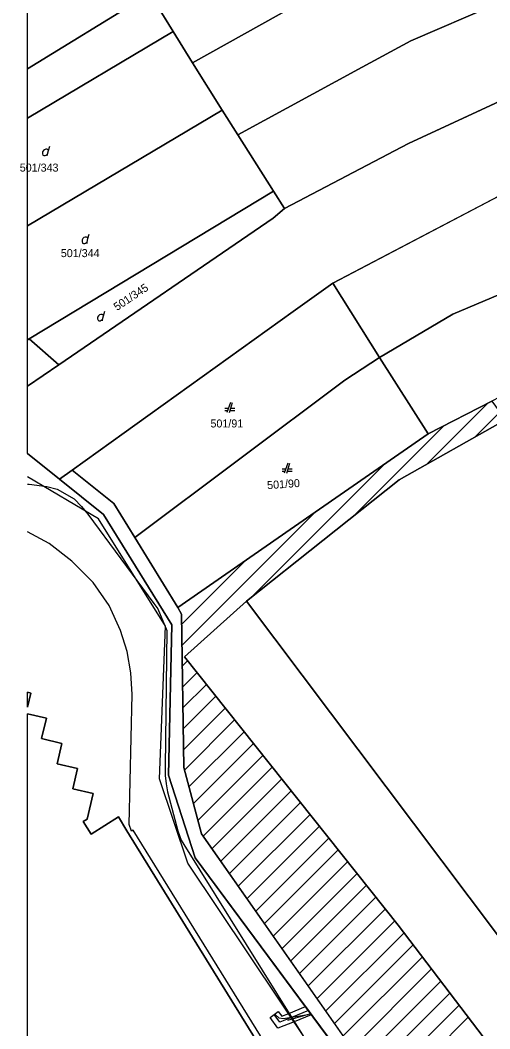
# Model space of a CAD drawing. Extents: x -264309 to -263505, y -1242443 to -1241763.
# Drawn here: x -264309.2 to -264215.4, y -1242302.6 to -1242101 of the extents above; entities that cross this region are included whole.
import ezdxf

# ---------------------------------------------------------------- set-up
doc = ezdxf.new("R2010")
doc.units = 0
for name, color, linetype in [('KN_2019_08_16', 7, 'Continuous'), ('KN_2019_08_16_KLADPAR', 7, 'Continuous'), ('KN_2019_08_16_ZAPPAR', 7, 'Continuous'), ('SRAFY_PARCELY', 7, 'Continuous')]:
    doc.layers.add(name, color=color, linetype=linetype)

msp = doc.modelspace()

# ---------------------------------------------------------------- linework, layer by layer
at = {"layer": 'KN_2019_08_16'}
msp.add_line((-264252.15, -1242299.89), (-264255.82, -1242300.96), dxfattribs=at)
for points in [[(-264307.74, -1242340.12), (-264306.25, -1242339.09), (-264251.27, -1242306.11), (-264275.75, -1242269.48), (-264281.42, -1242252.63), (-264280.19, -1242222.16), (-264293.61, -1242200.69), (-264307.74, -1242192.28)], [(-264251.64, -1242298.97), (-264255.03, -1242300.37), (-264257.35, -1242301.31), (-264258.47, -1242299.75)], [(-264251.16, -1242299.61), (-264252.15, -1242299.89), (-264256.65, -1242300.61), (-264257.51, -1242300.5), (-264258.32, -1242299.77)]]:
    msp.add_lwpolyline(points, dxfattribs=at)
msp.add_lwpolyline([(-264250.88, -1242299.99), (-264251.12, -1242299.83), (-264254.5, -1242301.21), (-264257.75, -1242302.51), (-264259.27, -1242300.35), (-264258.47, -1242299.75), (-264257.67, -1242299.15), (-264256.96, -1242300.09), (-264255.56, -1242299.52), (-264252.24, -1242298.16), (-264251.64, -1242298.97)], close=True, dxfattribs=at)
at = {"layer": 'KN_2019_08_16_KLADPAR'}
for p, q in [((-264307.74, -1242110.73), (-264307.74, -1242064.3)), ((-264307.74, -1242110.73), (-264283.31, -1242095.71)), ((-264283.31, -1242095.71), (-264307.74, -1242110.73)), ((-264283.31, -1242095.71), (-264278.66, -1242103.27)), ((-264278.66, -1242103.27), (-264307.74, -1242120.6)), ((-264307.74, -1242120.6), (-264278.66, -1242103.27)), ((-264278.66, -1242103.27), (-264274.79, -1242109.56)), ((-264274.79, -1242109.56), (-264268.86, -1242119.03)), ((-264231.66, -1242125.67), (-264195.32, -1242108.83)), ((-264307.74, -1242120.6), (-264307.74, -1242110.73)), ((-264268.86, -1242119.03), (-264307.74, -1242142.14)), ((-264307.74, -1242142.14), (-264268.86, -1242119.03)), ((-264268.86, -1242119.03), (-264265.78, -1242123.95)), ((-264307.74, -1242142.14), (-264307.74, -1242120.6)), ((-264265.78, -1242123.95), (-264258.61, -1242135.22)), ((-264303.59, -1242127.11), (-264303.32, -1242126.21)), ((-264256.42, -1242138.67), (-264231.66, -1242125.67)), ((-264207.96, -1242133.21), (-264246.81, -1242153.57)), ((-264258.61, -1242135.22), (-264307.46, -1242164.74)), ((-264301.53, -1242169.89), (-264258.73, -1242140.63)), ((-264258.73, -1242140.63), (-264256.42, -1242138.67)), ((-264307.74, -1242164.9), (-264307.74, -1242142.14)), ((-264295.7, -1242144.67), (-264295.43, -1242143.77)), ((-264246.81, -1242153.57), (-264254.72, -1242159.25)), ((-264254.72, -1242159.25), (-264298.85, -1242190.99)), ((-264292.59, -1242160.11), (-264292.32, -1242159.21)), ((-264307.46, -1242164.74), (-264307.74, -1242164.9)), ((-264307.74, -1242164.9), (-264307.46, -1242164.74)), ((-264307.46, -1242164.74), (-264301.53, -1242169.89)), ((-264307.74, -1242174.19), (-264307.74, -1242164.9)), ((-264301.53, -1242169.89), (-264307.74, -1242174.19)), ((-264307.74, -1242174.19), (-264301.53, -1242169.89)), ((-264307.74, -1242187.65), (-264307.74, -1242174.19)), ((-264267.65, -1242178.64), (-264268.33, -1242178.64)), ((-264267.23, -1242177.44), (-264267.93, -1242179.44)), ((-264267.43, -1242179.44), (-264266.83, -1242177.44)), ((-264266.33, -1242178.64), (-264267.19, -1242178.64)), ((-264268.33, -1242179.04), (-264267.79, -1242179.04)), ((-264267.31, -1242179.04), (-264266.33, -1242179.04)), ((-264301.35, -1242192.78), (-264307.74, -1242187.65)), ((-264301.35, -1242192.78), (-264298.85, -1242190.99)), ((-264298.85, -1242190.99), (-264301.35, -1242192.78)), ((-264298.85, -1242190.99), (-264290.49, -1242197.63)), ((-264256.22, -1242190.76), (-264256.9, -1242190.76)), ((-264255.8, -1242189.56), (-264256.5, -1242191.56)), ((-264256, -1242191.56), (-264255.4, -1242189.56)), ((-264254.9, -1242190.76), (-264255.76, -1242190.76)), ((-264292.61, -1242199.8), (-264301.35, -1242192.78)), ((-264256.9, -1242191.16), (-264256.36, -1242191.16)), ((-264255.88, -1242191.16), (-264254.9, -1242191.16)), ((-264290.49, -1242197.63), (-264286.35, -1242204.42)), ((-264278.94, -1242221.86), (-264292.61, -1242199.8)), ((-264286.35, -1242204.42), (-264277.77, -1242218.42)), ((-264277.77, -1242218.42), (-264276.98, -1242219.72)), ((-264276.98, -1242219.72), (-264276.57, -1242250.38)), ((-264279.62, -1242251.94), (-264278.94, -1242221.86)), ((-264307.74, -1242238.35), (-264307.74, -1242235.36)), ((-264307.74, -1242235.36), (-264307.08, -1242235.52)), ((-264307.08, -1242235.52), (-264307.74, -1242238.35)), ((-264307.74, -1242332.8), (-264307.74, -1242239.64)), ((-264307.74, -1242239.64), (-264303.98, -1242240.53)), ((-264303.98, -1242240.53), (-264304.95, -1242244.6)), ((-264304.95, -1242244.6), (-264300.88, -1242245.57)), ((-264300.88, -1242245.57), (-264301.83, -1242249.65)), ((-264301.83, -1242249.65), (-264297.75, -1242250.6)), ((-264297.75, -1242250.6), (-264298.7, -1242254.62)), ((-264276.57, -1242250.38), (-264272.98, -1242263.62)), ((-264274.26, -1242268.44), (-264279.62, -1242251.94)), ((-264298.7, -1242254.62), (-264294.68, -1242255.57)), ((-264294.68, -1242255.57), (-264295.87, -1242260.74)), ((-264295.87, -1242260.74), (-264296.63, -1242261.2)), ((-264296.63, -1242261.2), (-264295.08, -1242263.7)), ((-264295.08, -1242263.7), (-264289.57, -1242260.22)), ((-264289.57, -1242260.22), (-264287.91, -1242263.04)), ((-264287.91, -1242263.04), (-264262.22, -1242304.65)), ((-264272.98, -1242263.62), (-264240.46, -1242310.08)), ((-264240.44, -1242314.08), (-264274.26, -1242268.44))]:
    msp.add_line(p, q, dxfattribs=at)
for points in [[(-264232.73, -1242069.28), (-264215.64, -1242060.08), (-264203.07, -1242053.35), (-264189.98, -1242046.97), (-264181.27, -1242051.82), (-264173.43, -1242055.54), (-264168.01, -1242057.92), (-264176.29, -1242061.5), (-264207.3, -1242075.14), (-264227.48, -1242084.41), (-264254.05, -1242097.99), (-264274.79, -1242109.56), (-264278.66, -1242103.27), (-264283.31, -1242095.71), (-264271.31, -1242088.83)], [(-264168.01, -1242057.92), (-264161.74, -1242060.05), (-264155.45, -1242062), (-264148.68, -1242063.74), (-264141.87, -1242065.13), (-264136.47, -1242066.18), (-264140.89, -1242068), (-264182.59, -1242084.17), (-264197.75, -1242090.71), (-264231.21, -1242105.15), (-264240.95, -1242110.43), (-264265.78, -1242123.95), (-264268.86, -1242119.03), (-264274.79, -1242109.56), (-264254.05, -1242097.99), (-264227.48, -1242084.41), (-264207.3, -1242075.14), (-264176.29, -1242061.5)], [(-264136.47, -1242066.18), (-264126.66, -1242067.07), (-264113.43, -1242067.44), (-264093.07, -1242066.63), (-264091, -1242071.24), (-264106.54, -1242077.18), (-264118.83, -1242081.48), (-264143.3, -1242090.1), (-264171.23, -1242099.67), (-264195.32, -1242108.83), (-264231.66, -1242125.67), (-264256.42, -1242138.67), (-264258.61, -1242135.22), (-264265.78, -1242123.95), (-264240.95, -1242110.43), (-264231.21, -1242105.15), (-264197.75, -1242090.71), (-264182.59, -1242084.17), (-264140.89, -1242068)], [(-264246.81, -1242153.57), (-264207.96, -1242133.21), (-264176.83, -1242121.28), (-264120.91, -1242102.78), (-264081.08, -1242089.93), (-264076.9, -1242098.2), (-264076.93, -1242111.1), (-264102.41, -1242118.92), (-264128.45, -1242126.51), (-264158.28, -1242134.19), (-264188.56, -1242145.27), (-264215.11, -1242156.51), (-264222.8, -1242159.81), (-264237.43, -1242168.42)], [(-264076.93, -1242111.1), (-264076.98, -1242129.46), (-264076.3, -1242133.7), (-264095.55, -1242140.08), (-264157.05, -1242153.68), (-264195.05, -1242168.92), (-264211.96, -1242175.6), (-264215.03, -1242177.17), (-264227.71, -1242183.68), (-264237.43, -1242168.42), (-264222.8, -1242159.81), (-264215.11, -1242156.51), (-264188.56, -1242145.27), (-264158.28, -1242134.19), (-264128.45, -1242126.51), (-264102.41, -1242118.92)], [(-264307.46, -1242164.74), (-264258.61, -1242135.22), (-264256.42, -1242138.67), (-264258.73, -1242140.63), (-264301.53, -1242169.89)], [(-264298.85, -1242190.99), (-264254.72, -1242159.25), (-264246.81, -1242153.57), (-264237.43, -1242168.42), (-264244.4, -1242173), (-264286.35, -1242204.42), (-264290.49, -1242197.63)], [(-264237.43, -1242168.42), (-264227.71, -1242183.68), (-264255.3, -1242202.84), (-264277.77, -1242218.42), (-264286.35, -1242204.42), (-264244.4, -1242173)], [(-264264.01, -1242217.15), (-264233.51, -1242192.88), (-264212.29, -1242180.92), (-264137.78, -1242284.52), (-264187.74, -1242315.7), (-264213.92, -1242283.84)], [(-264187.74, -1242315.7), (-264201.06, -1242324.01), (-264208.73, -1242314.82), (-264233.72, -1242281.89), (-264276.4, -1242228.3), (-264264.01, -1242217.15), (-264213.92, -1242283.84)]]:
    msp.add_lwpolyline(points, close=True, dxfattribs=at)
for points in [[(-264303.77, -1242128.1), (-264303.77, -1242127.83), (-264303.59, -1242127.11), (-264303.68, -1242126.93), (-264303.86, -1242126.84), (-264304.13, -1242126.84), (-264304.4, -1242126.93), (-264304.58, -1242127.11), (-264304.76, -1242127.38), (-264304.76, -1242127.74), (-264304.67, -1242128.01), (-264304.49, -1242128.1), (-264304.22, -1242128.1), (-264304.04, -1242128.01), (-264303.77, -1242127.83)], [(-264295.88, -1242145.66), (-264295.88, -1242145.39), (-264295.7, -1242144.67), (-264295.79, -1242144.49), (-264295.97, -1242144.4), (-264296.24, -1242144.4), (-264296.51, -1242144.49), (-264296.69, -1242144.67), (-264296.87, -1242144.94), (-264296.87, -1242145.3), (-264296.78, -1242145.57), (-264296.6, -1242145.66), (-264296.33, -1242145.66), (-264296.15, -1242145.57), (-264295.88, -1242145.39)], [(-264292.77, -1242161.1), (-264292.77, -1242160.83), (-264292.59, -1242160.11), (-264292.68, -1242159.93), (-264292.86, -1242159.84), (-264293.13, -1242159.84), (-264293.4, -1242159.93), (-264293.58, -1242160.11), (-264293.76, -1242160.38), (-264293.76, -1242160.74), (-264293.67, -1242161.01), (-264293.49, -1242161.1), (-264293.22, -1242161.1), (-264293.04, -1242161.01), (-264292.77, -1242160.83)], [(-264240.46, -1242310.08), (-264272.98, -1242263.62), (-264276.57, -1242250.38), (-264276.98, -1242219.72), (-264277.77, -1242218.42), (-264255.3, -1242202.84), (-264227.71, -1242183.68), (-264215.03, -1242177.17), (-264212.29, -1242180.92), (-264233.51, -1242192.88), (-264264.01, -1242217.15), (-264276.4, -1242228.3), (-264233.72, -1242281.89), (-264208.73, -1242314.82)], [(-264307.74, -1242187.65), (-264301.35, -1242192.78), (-264292.61, -1242199.8), (-264278.94, -1242221.86), (-264279.62, -1242251.94), (-264274.26, -1242268.44), (-264240.44, -1242314.08)], [(-264307.74, -1242238.35), (-264307.08, -1242235.52), (-264307.74, -1242235.36)], [(-264287.91, -1242263.04), (-264289.57, -1242260.22), (-264295.08, -1242263.7), (-264296.63, -1242261.2), (-264295.87, -1242260.74), (-264294.68, -1242255.57), (-264298.7, -1242254.62), (-264297.75, -1242250.6), (-264301.83, -1242249.65), (-264300.88, -1242245.57), (-264304.95, -1242244.6), (-264303.98, -1242240.53), (-264307.74, -1242239.64)], [(-264307.74, -1242332.8), (-264294.78, -1242324.78), (-264285.87, -1242319.27), (-264284.51, -1242318.43), (-264262.22, -1242304.65), (-264287.91, -1242263.04)]]:
    msp.add_lwpolyline(points, dxfattribs=at)
at = {"layer": 'KN_2019_08_16_ZAPPAR'}
for p, q in [((-264295.7, -1242199.76), (-264282.5, -1242217.61)), ((-264291.44, -1242218.02), (-264294.67, -1242213.4)), ((-264276.56, -1242265.77), (-264251.67, -1242305.76))]:
    msp.add_line(p, q, dxfattribs=at)
for points in [[(-264307.74, -1242193.79), (-264307.44, -1242193.76), (-264303.91, -1242194.2), (-264301.85, -1242194.77), (-264298.47, -1242196.7), (-264296.96, -1242198.2), (-264295.7, -1242199.76)], [(-264294.67, -1242213.4), (-264298.91, -1242209.14), (-264303.46, -1242205.59), (-264307.74, -1242203.26)], [(-264294.08, -1242327.76), (-264281.99, -1242320.38), (-264276.84, -1242315.01), (-264261.64, -1242305.63), (-264261.11, -1242304.9), (-264261.26, -1242304), (-264286.65, -1242262.93), (-264286.99, -1242263.13), (-264287.49, -1242261.77), (-264286.83, -1242235.8), (-264287.1, -1242231.47), (-264287.89, -1242227.2), (-264289.22, -1242223), (-264291.44, -1242218.02)], [(-264282.5, -1242217.61), (-264281.73, -1242218.7), (-264279.94, -1242223.04), (-264280.27, -1242250.24), (-264280.24, -1242251.96), (-264280.08, -1242253.64), (-264279.79, -1242255.28), (-264277.72, -1242263.06), (-264277.43, -1242264), (-264277.04, -1242264.91), (-264276.56, -1242265.77)]]:
    msp.add_lwpolyline(points, dxfattribs=at)
at = {"layer": 'SRAFY_PARCELY'}
for p, q in [((-264228.05, -1242189.8), (-264215.82, -1242177.58)), ((-264218.33, -1242184.32), (-264213.4, -1242179.4)), ((-264242.61, -1242200.12), (-264224.54, -1242182.05)), ((-264263.38, -1242216.65), (-264236.55, -1242189.82)), ((-264276.9, -1242225.92), (-264250.44, -1242199.46)), ((-264276.95, -1242221.74), (-264264.29, -1242209.07)), ((-264276.84, -1242230.11), (-264275.79, -1242229.06)), ((-264276.79, -1242234.3), (-264273.91, -1242231.42)), ((-264276.73, -1242238.48), (-264272.03, -1242233.79)), ((-264276.67, -1242242.67), (-264270.15, -1242236.15)), ((-264276.62, -1242246.86), (-264268.27, -1242238.51)), ((-264276.43, -1242250.91), (-264266.39, -1242240.87)), ((-264275.52, -1242254.25), (-264264.51, -1242243.23)), ((-264274.62, -1242257.58), (-264262.63, -1242245.59)), ((-264273.71, -1242260.92), (-264260.75, -1242247.96)), ((-264272.65, -1242264.1), (-264258.87, -1242250.32)), ((-264270.9, -1242266.59), (-264256.98, -1242252.68)), ((-264269.15, -1242269.09), (-264255.1, -1242255.04)), ((-264267.4, -1242271.58), (-264253.22, -1242257.4)), ((-264265.66, -1242274.08), (-264251.34, -1242259.76)), ((-264263.91, -1242276.58), (-264249.46, -1242262.13)), ((-264262.16, -1242279.07), (-264247.58, -1242264.49)), ((-264260.42, -1242281.57), (-264245.7, -1242266.85)), ((-264258.67, -1242284.06), (-264243.82, -1242269.21)), ((-264256.92, -1242286.56), (-264241.94, -1242271.57)), ((-264255.18, -1242289.05), (-264240.06, -1242273.93)), ((-264253.43, -1242291.55), (-264238.18, -1242276.3)), ((-264251.68, -1242294.05), (-264236.29, -1242278.66)), ((-264249.94, -1242296.54), (-264234.41, -1242281.02)), ((-264248.19, -1242299.04), (-264232.56, -1242283.41)), ((-264246.44, -1242301.53), (-264230.73, -1242285.83)), ((-264244.7, -1242304.03), (-264228.9, -1242288.24)), ((-264242.95, -1242306.53), (-264227.07, -1242290.65)), ((-264241.2, -1242309.02), (-264225.24, -1242293.06)), ((-264239.35, -1242311.41), (-264223.41, -1242295.47)), ((-264237.43, -1242313.73), (-264221.58, -1242297.89)), ((-264235.5, -1242316.05), (-264219.75, -1242300.3))]:
    msp.add_line(p, q, dxfattribs=at)

# ---------------------------------------------------------------- texts
at = {"layer": 'KN_2019_08_16_KLADPAR'}
for s, p in [('501/343', (-264309.31, -1242131.3)), ('501/344', (-264301.11, -1242148.39)), ('501/91', (-264271.22, -1242182.43))]:
    msp.add_text(s, height=1.6, dxfattribs=at).set_placement(p)
for s, rotation, p in [('501/345', 33.6899, (-264289.89, -1242159.18)), ('501/90', 3.9534, (-264259.84, -1242194.77))]:
    msp.add_text(s, height=1.6, rotation=rotation, dxfattribs=at).set_placement(p)

doc.saveas('drawing.dxf')
